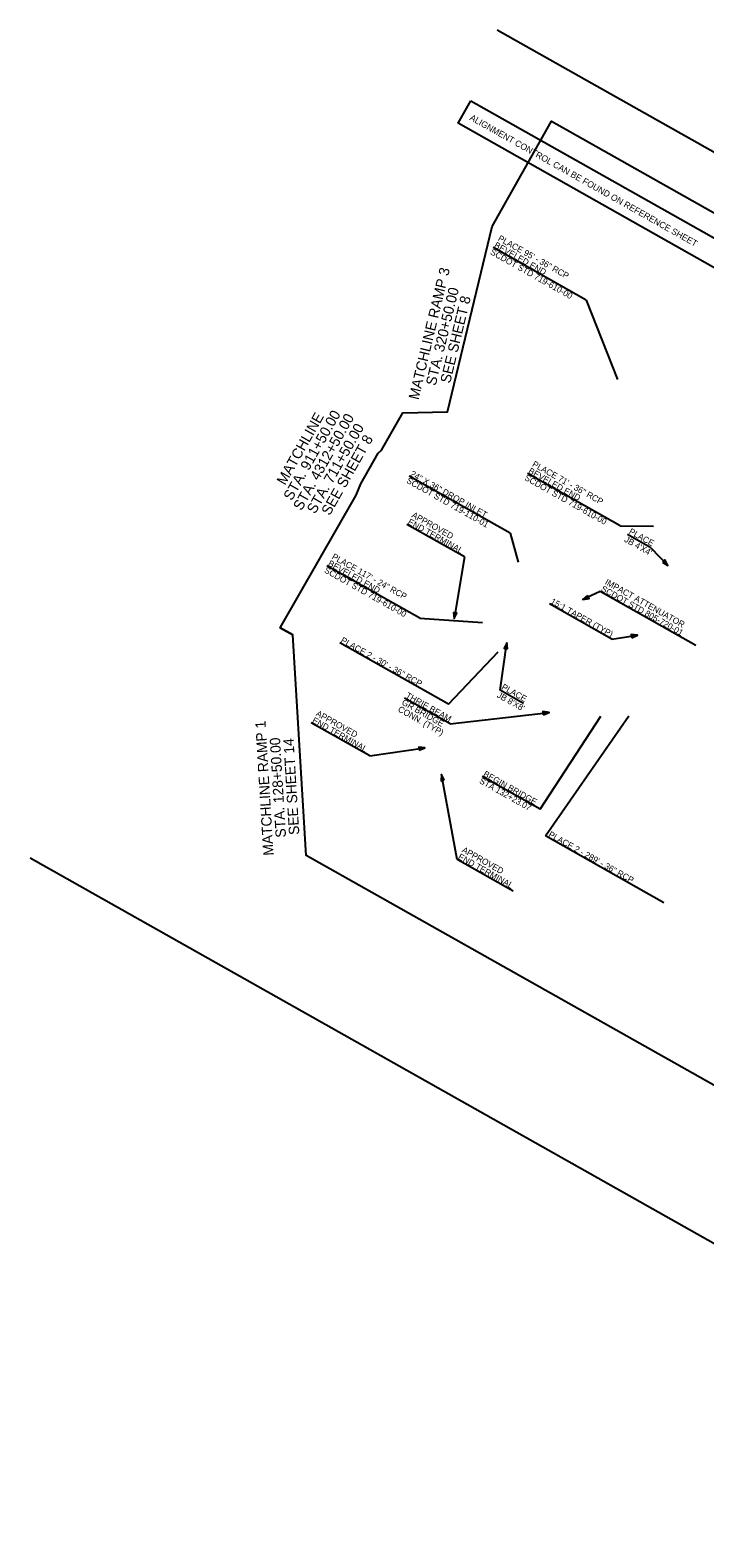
# Model space of a CAD drawing. Extents: x 2220413 to 2222436, y 468301 to 470126.
# Drawn here: x 2220413 to 2221229, y 468301 to 470126 of the extents above; entities that cross this region are included whole.
import ezdxf

# ---------------------------------------------------------------- set-up
doc = ezdxf.new("R2010")
doc.units = 0
for name, color, linetype in [('RD_HY_Misc', 7, 'Continuous'), ('RD_PD_Final_TX', 7, 'Continuous'), ('RD_SHT_MatchLine', 7, 'Continuous'), ('RD_SHT_ShtClip', 7, 'Continuous'), ('RD_SHT_TX', 7, 'Continuous')]:
    doc.layers.add(name, color=color, linetype=linetype)

msp = doc.modelspace()

# ---------------------------------------------------------------- linework, layer by layer
at = {"layer": 'RD_HY_Misc'}
for p, q in [((2221085, 469799.1), (2220972.6, 469862.6)), ((2220993.3, 469517), (2220871.2, 469585.9)), ((2221126.4, 469525.9), (2221014, 469589.3)), ((2221163.5, 469499.4), (2221135.2, 469515.4)), ((2220884, 469414), (2220771.6, 469477.4)), ((2220918.5, 469310.3), (2220787, 469384.4)), ((2221009.4, 469311.1), (2220981.1, 469327)), ((2221179.1, 469069.8), (2221035.8, 469150.7))]:
    msp.add_line(p, q, dxfattribs=at)
for points in [[(2221085, 469799.1), (2221123, 469703)], [(2221126.4, 469525.9), (2221166.8, 469525.7)], [(2220993.3, 469517), (2221002.7, 469482)], [(2221163.5, 469499.4), (2221184.1, 469478)], [(2220884, 469414), (2220959.6, 469408.8)], [(2220981.1, 469327), (2220989.1, 469384.4)], [(2220918.5, 469310.3), (2220978.6, 469373.5)], [(2221035.8, 469150.7), (2221136.8, 469296.2)]]:
    msp.add_lwpolyline(points, dxfattribs=at)
for points in [[(2221177.7, 469481.9), (2221184.1, 469478), (2221180.5, 469484.6)], [(2220990, 469376.9), (2220989.1, 469384.4), (2220986.1, 469377.4)]]:
    msp.add_lwpolyline(points, close=True, dxfattribs=at)
at = {"layer": 'RD_PD_Final_TX'}
for p, q in [((2220938, 469488.3), (2220868.1, 469527.7)), ((2221217.7, 469381.3), (2221101.9, 469446.6)), ((2221116.2, 469388.9), (2221040.7, 469431.5)), ((2220920.8, 469286.3), (2220865.5, 469317.5)), ((2220823.3, 469247.4), (2220752.4, 469287.4)), ((2221029.6, 469182.9), (2220959.4, 469222.5)), ((2220996.9, 469083.9), (2220928.9, 469122.3))]:
    msp.add_line(p, q, dxfattribs=at)
for points in [[(2220938, 469488.3), (2220925.5, 469413.6)], [(2221101.9, 469446.6), (2221081.2, 469436.8)], [(2221116.2, 469388.9), (2221147.2, 469393.5)], [(2220920.8, 469286.3), (2221040.2, 469300.1)], [(2221029.6, 469182.9), (2221103.1, 469295.5)], [(2220823.3, 469247.4), (2220890, 469257.3)], [(2220928.9, 469122.3), (2220910.2, 469225)]]:
    msp.add_lwpolyline(points, dxfattribs=at)
for points in [[(2221086.9, 469441.6), (2221081.2, 469436.8), (2221088.6, 469438.1)], [(2220924.8, 469421), (2220925.5, 469413.6), (2220928.6, 469420.4)], [(2221140.3, 469390.5), (2221147.2, 469393.5), (2221139.7, 469394.3)], [(2221033.2, 469297.4), (2221040.2, 469300.1), (2221032.8, 469301.2)], [(2220883.2, 469254.3), (2220890, 469257.3), (2220882.6, 469258.2)], [(2220913.4, 469218.2), (2220910.2, 469225), (2220909.6, 469217.5)]]:
    msp.add_lwpolyline(points, close=True, dxfattribs=at)
at = {"layer": 'RD_SHT_MatchLine'}
for p, q in [((2220971.4, 469888.1), (2221043.3, 470015.5)), ((2220917.6, 469663.8), (2220971.4, 469888.1)), ((2220863.4, 469662.8), (2220917.6, 469663.8)), ((2220715, 469402.7), (2220730.3, 469394)), ((2220746.6, 469127.1), (2220730.3, 469394))]:
    msp.add_line(p, q, dxfattribs=at)
msp.add_lwpolyline([(2220715, 469402.7), (2220761.1, 469482.9), (2220807.1, 469563.1), (2220812.4, 469576.7), (2220833.7, 469613.8), (2220837.4, 469617.6), (2220863.4, 469662.8)], dxfattribs=at)
at = {"layer": 'RD_SHT_ShtClip'}
msp.add_lwpolyline([(2221423.4, 468745.3), (2220746.6, 469127.1), (2220730.3, 469394), (2220715, 469402.7), (2220761.1, 469482.9), (2220807.1, 469563.1), (2220812.4, 469576.7), (2220833.7, 469613.8), (2220837.4, 469617.6), (2220863.4, 469662.8), (2220917.6, 469663.8), (2220971.4, 469888.1), (2221043.3, 470015.5), (2221374.2, 469828.9)], dxfattribs=at)
at = {"layer": 'RD_SHT_TX'}
for p, q in [((2222436.4, 469302.8), (2220977.6, 470125.8)), ((2220412.5, 469124.2), (2221871.4, 468301.2))]:
    msp.add_line(p, q, dxfattribs=at)
msp.add_lwpolyline([(2220945.5, 470040.3), (2221287.6, 469847.3), (2221272.3, 469820.2), (2220930.2, 470013.2)], close=True, dxfattribs=at)

# ---------------------------------------------------------------- texts
at = {"layer": 'RD_HY_Misc'}
for s, p in [('PLACE 95\' - 36" RCP', (2220977.7, 469871.7)), ('SCDOT STD 719-610-00', (2220968.4, 469855.1)), ('BEVELED END', (2220973.1, 469863.4)), ('PLACE 71\' - 36" RCP', (2221019.2, 469598.4)), ('SCDOT STD 719-110-01', (2220867, 469578.5)), ('24" X 36" DROP INLET', (2220871.6, 469586.7)), ('SCDOT STD 719-610-00', (2221009.8, 469581.9)), ('BEVELED END', (2221014.5, 469590.2)), ("JB 4'X4'", (2221130.6, 469507.2)), ('PLACE', (2221136.1, 469517)), ('PLACE 117\' - 24" RCP', (2220776.7, 469486.4)), ('SCDOT STD 719-610-00', (2220767.5, 469470.1)), ('BEVELED END', (2220772.1, 469478.3)), ('PLACE 2 - 30\' - 36" RCP', (2220787.5, 469385.3)), ('PLACE', (2220982, 469328.7)), ("JB 8'X8'", (2220976.5, 469318.9)), (' PLACE 2 - 289\' - 36" RCP', (2221036.3, 469151.6))]:
    msp.add_text(s, height=7.5, rotation=330.5715, dxfattribs=at).set_placement(p)
at = {"layer": 'RD_PD_Final_TX'}
for s, p in [('END TERMINAL', (2220868.6, 469528.5)), ('APPROVED', (2220873.3, 469536.8)), ('SCDOT STD 805-720-01', (2221102.4, 469447.5)), ('IMPACT ATTENUATOR', (2221107.1, 469455.8)), ('15:1 TAPER (TYP)', (2221041.2, 469432.4)), ('CONN. (TYP)', (2220856.7, 469301.8)), ('GR BRIDGE ', (2220861.3, 469310.1)), ('THRIE BEAM', (2220866, 469318.4)), ('END TERMINAL', (2220752.9, 469288.3)), ('APPROVED', (2220757.5, 469296.6)), ('STA 132+23.07', (2220955.2, 469215.1)), ('BEGIN BRIDGE', (2220959.9, 469223.4)), ('END TERMINAL', (2220929.4, 469123.2)), ('APPROVED', (2220934.1, 469131.5))]:
    msp.add_text(s, height=7.5, rotation=330.5715, dxfattribs=at).set_placement(p)
at = {"layer": 'RD_SHT_MatchLine'}
for s, rotation, p in [('MATCHLINE RAMP 3 ', 76.5039, (2220882.3, 469677.8)), ('STA. 320+50.00', 76.5039, (2220903.1, 469694.8)), ('SEE SHEET 8', 76.5039, (2220920.6, 469697.7)), ('MATCHLINE', 60.5715, (2220720.9, 469574.3)), ('STA. 911+50.00', 60.5715, (2220729, 469555.6)), ('STA. 4312+50.00', 60.5715, (2220740.8, 469543.5)), ('STA. 711+50.00', 60.5715, (2220757.3, 469539.6)), ('SEE SHEET 8', 60.5715, (2220774.9, 469537.6)), ('MATCHLINE RAMP 1', 93.4875, (2220707.1, 469127.2)), ('STA. 128+50.00', 93.4875, (2220722.1, 469149)), ('SEE SHEET 14', 93.4875, (2220738.2, 469152.3))]:
    msp.add_text(s, height=12.5, rotation=rotation, dxfattribs=at).set_placement(p)
at = {"layer": 'RD_SHT_TX'}
msp.add_text('ALIGNMENT CONTROL CAN BE FOUND ON REFERENCE SHEET', height=7.656, rotation=330.5715, dxfattribs=at).set_placement((2220943.5, 470017.7))

doc.saveas('drawing.dxf')
